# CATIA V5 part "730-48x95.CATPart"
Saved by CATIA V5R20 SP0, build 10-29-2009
Part number: 730-48x95
Definition: NONE
Nomenclature: 730-48x95
Source: Unknown
Description: 730-48x95
Bounding box of the stored display mesh (mm): x -28 to 28, y -27.5 to 27.5, z 0 to 95
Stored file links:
  C:\Users\Utente\Desktop\IO LAVORO\3D X SITO CF\X SITO\730\730-48x95.CATPart
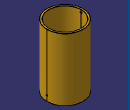
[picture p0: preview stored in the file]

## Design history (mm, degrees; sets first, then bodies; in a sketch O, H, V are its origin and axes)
Body1 "730-48x95" (main body)
  Solid1: solid without history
